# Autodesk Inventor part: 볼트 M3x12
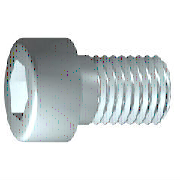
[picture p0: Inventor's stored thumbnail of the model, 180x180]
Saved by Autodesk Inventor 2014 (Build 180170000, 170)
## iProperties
IsCustomPart: 0
Created: 2012-02
Part Number: 볼트 M3x12
Material: 강철, 연강
Description: 6각머리 태핑 나사
Document SubType Name: Modeling
Standard: KS B 1003
Designer: mduedu
Standards Organization: KS
Language: ko-KR
Size Designation: M 3 x 12
Categories: <MemberInstance><Categories><Category DisplayName="조임쇠" InternalName="e4da775c-781d-43d5-af7c-5136215cf5a6" Mnemonic="FSTN"><Category DisplayName="볼트" InternalN
Density: 1 g/cm^3
Appearance: Steel
Author: mduedu
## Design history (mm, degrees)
sketch "스케치1"
  geometry: L1 (-0.867, 0)-(12, 0); L2 (12, 0)-(12, 1.5); L3 (12, 1.5)-(1.25, 1.5); L4 (1.25, 1.5)-(0.943, 1.5); L5 (0.943, 1.5)-(0, 1.5); L6 (0, 1.5)-(0, 2.75); L7 (0, 2.75)-(-3, 2.75); L8 (-3, 2.75)-(-3, 1.443); L9 (-3, 1.443)-(-1.7, 1.443); L10 (-1.7, 1.443)-(-0.867, 0); L11 (-6, 0)-(15, 0) reference; L12 (0, -0.55)-(0, 3.3) reference; L13 (1.25, 1.5)-(0, 1.5)
  constraints: 22 end point, 6 parallel, 2 collinear, 2 perpendicular, 1 horizontal, 1 point on line
  dimensions: "d1" = 10.75 distance from line of L3.end L2 (= GEL); "d2" = 0.30683 distance of L4.end L3.end (computed from GAL); "d3" = 3 distance between parallel lines of L8 L6 (= KOH); "d4" = 1.3 distance of L8.end L9.end (= INTI); "d5" = 60 deg angle of L10 L1; "d6" = 3 diameter of L3 L1 (= GD); "d7" = 3 diameter of L5 L1 (= BDM); "d8" = 2.88675 diameter of L9 L1 (= 1.1547 x SW); "d9" = 5.5 diameter of L7 L1 (= KOD); "d26" = 12 distance between parallel lines of L12 L2 (= NLG)
revolve "본체" sketch "스케치1" stored, may be unused: angle "d10" = 90 deg
sketch "스케치2"
  geometry: L1 (0, -3.85)-(0, 3.85) reference; L2 (-3.85, 0)-(3.85, 0) reference; L3 (1.443, 0)-(0.722, -1.25); L4 (0.722, -1.25)-(-0.722, -1.25); L5 (-0.722, -1.25)-(-1.443, 0); L6 (-1.443, 0)-(-0.722, 1.25); L7 (-0.722, 1.25)-(0.722, 1.25); L8 (0.722, 1.25)-(1.443, 0); 2 further points
  constraints: 12 end point, 1 coincident, 1 horizontal alignment, 1 point on line, 12 other
extrude "슬롯" join sketch "스케치2" stored distance "d11" = 10; taper "d12" = 0 deg
workplane "Work Plane1"
fillet "Fillet2" dims "d30" = 0.1 (= R)
body "Solid1"
fillet "모깎기1" dims "d17" = 0.3 (= RR)
feature "스레드" dims "d13" = 10.75 (= GEL), "d14" = 0
chamfer "모따기1" distance "d15" = 0.30673 (= -0.5 x SPD + 0.5 x GD); stored, may be unused: second distance "d16" = 0.30673 (= GUL), angle "d27" = 45 deg
other parameters: "GD" = 3 (= NND) [user parameter; used in 2 equation terms], "NLG" = 12 [user parameter; used in 1 equation term], "GEL" = 10.75 [user parameter; used in 2 equation terms], "KOD" = 5.5 [user parameter; used in 1 equation term], "KOH" = 3 [user parameter; used in 1 equation term], "INTI" = 1.3 [user parameter; used in 1 equation term], "GAL" = 0.30673 (= 0.61345 x PTC) [user parameter; used in 1 equation term], "GUL" = 0.30673 (= 0.61345 x PTC) [user parameter; used in 1 equation term], "BDM" = 3 (= NND) [user parameter; used in 1 equation term], "SW" = 2.5 [user parameter; used in 2 equation terms], "RR" = 0.3 [user parameter; used in 1 equation term], "SPD" = 2.38655 (= NND - 1.2269 x PTC) [user parameter; used in 1 equation term], "d19" = 0, "d28" = 0, "d29" = 0, "R" = 0.1 [user parameter; used in 1 equation term], "PHH" = 0.1 [user parameter], "GD1" = 2.38655 (= THREADDIA - 1.2269 x PTC) [user parameter], "THREADDIA" = 3 [user parameter; used in 1 equation term], "FAWI" = 45 deg [user parameter], "PTC" = 0.5 [user parameter; used in 5 equation terms], "NND" = 3 [user parameter; used in 3 equation terms], "TOA" = 30 deg [user parameter], "E0" = 2.8875 (= 1.155 x SW) [user parameter]
